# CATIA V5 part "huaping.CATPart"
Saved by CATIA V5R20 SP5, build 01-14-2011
Part number: 花瓶
Material "Walnut": density 609 kg/m3, Young's modulus 1.16e+10 Pa
Material "Light Green": density 7860 kg/m3, Young's modulus 2e+11 Pa, Poisson ratio 0.266
Material "Multicoloured Flag"
Material "Dark Green": density 7860 kg/m3, Young's modulus 2e+11 Pa, Poisson ratio 0.266
Material "China Blue": density 7860 kg/m3, Young's modulus 2e+11 Pa, Poisson ratio 0.266
Material "DS star": density 1000 kg/m3
Material "Ground Camouflage": density 7860 kg/m3, Young's modulus 2e+11 Pa, Poisson ratio 0.266
Material "Slightly Cloudy"
Bounding box of the stored display mesh (mm): x -34.997 to 42.622, y -40.202 to 35.695, z -0.537 to 153.496
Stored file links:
  E:\3.8\huaping.CATPart
  C:\Program Files\Dassault Systemes\B20\intel_a\startup\materials\Catalog.CATMaterial
  C:\Program Files\Dassault Systemes\B20\intel_a\startup\materials\chessboard.jpg
  C:\Program Files\Dassault Systemes\B20\intel_a\startup\materials\DS_star.jpg
  C:\Program Files\Dassault Systemes\B20\intel_a\startup\materials\red_env_512x512.jpg
  C:\Program Files\Dassault Systemes\B20\intel_a\startup\materials\walnut.jpg
  C:\Program Files\Dassault Systemes\B20\intel_a\startup\materials\yellow_env_512x512.jpg
  C:\Program Files\Dassault Systemes\B20\intel_a\startup\materials\red_wood.jpg
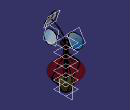
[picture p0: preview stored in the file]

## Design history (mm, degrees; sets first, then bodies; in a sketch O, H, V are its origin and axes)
Body1 (main body), material "Walnut"
  Plane1: type Offset, RefPlane xy-plane, Offset 20
  Plane2: type Offset, RefPlane Plane1, Offset 20
  Plane3: type Offset, RefPlane Plane2, Offset 20
  Plane4: type Offset, RefPlane Plane3, Offset 20
  Plane5: type Offset, RefPlane Plane4, Offset 20
  Sketch1 on xy-plane, origin (0, 0, 0), H (1, 0, 0), V (0, 1, 0)
    circle A1 centre (0, 0) radius 10
  Sketch2 on Plane1, origin (0, 0, 20), H (1, 0, 0), V (0, 1, 0)
    circle A1 centre (0, 0) radius 20
  Sketch3 on Plane2, origin (0, 0, 40), H (1, 0, 0), V (0, 1, 0)
    circle A1 centre (0, 0) radius 35
  Sketch4 on Plane3, origin (0, 0, 60), H (1, 0, 0), V (0, 1, 0)
    circle A1 centre (0, 0) radius 20
  Sketch5 on Plane4, origin (0, 0, 80), H (1, 0, 0), V (0, 1, 0)
    circle A1 centre (0, 0) radius 5
  Sketch6 on Plane5, origin (0, 0, 100), H (1, 0, 0), V (0, 1, 0)
    circle A1 centre (0, 0) radius 10
  Loft1: solid, Sections (Sketch1; Sketch2; Sketch3; Sketch4; Sketch5; Sketch6)
  Shell1: ExtOffset 0, Face face of Loft1, IntOffset 1
  Sketch7 on yz-plane, origin (0, 0, 0), H (0, 1, 0), V (0, 0, 1)
    axis line L1 (0, 0) -> (0, 29.7212)
    line L2 (0, 0) -> (0, 20.1202)
    line L3 (0, 20.1202) -> (16.3337, 20.1202)
    line L4 (16.3337, 20.1202) -> (9.3439, 2.1572)
    line L5 (9.3439, 2.1572) -> (0, 1.2281)
    point P5 (0, 1.2281)
    line L6 (0, 1.2281) -> (0, 2.1572)
    vertical: L1 V, L2 V, L6 V
    horizontal: L3 H
    coincidence: P5 L1
Body2, material "Light Green"
  Sketch8 on yz-plane, origin (0, 0, 0), H (0, 1, 0), V (0, 0, 1)
    axis line L1 (0, 0) -> (0, 30.1857)
    line L2 (0, 0) -> (0, 19.0363)
    line L3 (0, 19.0363) -> (15.2464, 19.0363)
    line L4 (15.2464, 19.0363) -> (9.1886, 0)
    point P4 (9.1886, 0)
    line L5 (9.1886, 0) -> (0, 0)
    vertical: L1 V, L2 V
    horizontal: L3 H, L5 H
    coincidence: P4 H
  Shaft1: profile Sketch8, axis Sketch8.L1, angle 360
Body3, material "Dark Green"
  Sketch9 on yz-plane, origin (0, 0, 0), H (0, 1, 0), V (0, 0, 1)
    spline S1 through (0, 0) (0, 59.8902) (8.0727, 104.7188) (25.6044, 121.7116)
    point P1 (0, 0)
    point P2 (0, 59.8902)
    coincidence: P1 O, P2 V
  Plane6: type Normal, Curve Sketch9, RefPoint vertex of Sketch9
  Sketch10 on Plane6, origin (0, 72.2974, 42.7547), H (1, 0, 0), V (0, -0.509, 0.8608)
    circle A1 centre (0, 91.5284) radius 0.5
    point P1 (0, 91.5284)
    coincidence: P1 V
  Rib1: profile Sketch10, centre curve Sketch9
Body4, material "Multicoloured Flag"
  Sketch11 on Plane6, origin (0, 72.2974, 42.7547), H (1, 0, 0), V (0, -0.509, 0.8608)
    spline S1 through (-10.9157, 92.9134) (12.7019, 103.5979) (15.6789, 82.031) (-6.9464, 74.1165) (-13.2973, 86.9775) (-10.9157, 92.9134)
    point P1 (-10.9157, 92.9134)
    point P2 (-10.9157, 92.9134)
    coincidence: P1 P2
  Pad1: profile Sketch11, direction (0, -0.8608, -0.509), length 1
Body5, material "China Blue"
  Sketch12 on yz-plane, origin (0, 0, 0), H (0, 1, 0), V (0, 0, 1)
    spline S1 through (2.4455, 0) (-2.1193, 60.2837) (-0.9285, 102.0326) (-35.2633, 133.2948)
    point P1 (2.4455, 0)
    coincidence: P1 H
  Plane7: type Normal, Curve Sketch12, RefPoint vertex of Sketch12
  Sketch13 on Plane7, origin (0, -72.4934, 24.8988), H (1, 0, 0), V (0, 0.3248, 0.9458)
    circle A1 centre (0, 113.78) radius 0.63
    point P1 (0, 113.78)
    coincidence: P1 V
  Rib2: profile Sketch13, centre curve Sketch12
Body6, material "DS star"
  Sketch14 on Plane7, origin (0, -72.4934, 24.8988), H (1, 0, 0), V (0, 0.3248, 0.9458)
    spline S1 through (-10.5028, 114.4599) (2.4929, 135.1086) (14.8795, 110.4111) (-1.5682, 102.516) (-10.5028, 114.4599)
    point P1 (-10.5028, 114.4599)
    point P2 (-10.5028, 114.4599)
    coincidence: P1 P2
  Pad2: profile Sketch14, direction (0, -0.9458, 0.3248), length 1
Body7
  Sketch15 on zx-plane, origin (0, 0, 0), H (-1, 0, 0), V (0, 0, 1)
    spline S1 through (0, 1.6227) (2.8578, 69.0544) (-27.9074, 131.9757) (-36.7297, 135.3586)
    point P1 (0, 1.6227)
    coincidence: P1 V
  Plane8: type Normal, Curve Sketch15, RefPoint vertex of Sketch15
Body8, material "Ground Camouflage"
  Sketch16 on Plane8, origin (68.5535, 0, 18.7011), H (0, 1, 0), V (-0.2632, 0, 0.9647)
    circle A1 centre (0, 120.6219) radius 0.516
    point P1 (0, 120.6219)
    coincidence: P1 V
  Rib3: profile Sketch16, centre curve Sketch15
Body9, material "Slightly Cloudy"
  Sketch17 on Plane8, origin (68.5535, 0, 18.7011), H (0, 1, 0), V (-0.2632, 0, 0.9647)
    spline S1 through (-13.6717, 110.6441) (-4.2521, 130.7953) (15.1758, 120.8176) (6.1487, 103.9923) (-13.6717, 110.6441)
    point P1 (-13.6717, 110.6441)
    point P2 (-13.6717, 110.6441)
    coincidence: P1 P2
  Pad3: profile Sketch17, direction (0.9647, 0, 0.2632), length 1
